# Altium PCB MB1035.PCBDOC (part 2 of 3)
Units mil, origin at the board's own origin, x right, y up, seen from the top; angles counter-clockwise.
Board outline 2598.43 x 3818.9 mil, 2 copper layers (TOP, Bottom); 145 components, 171 nets, 593 pads, 200 vias.
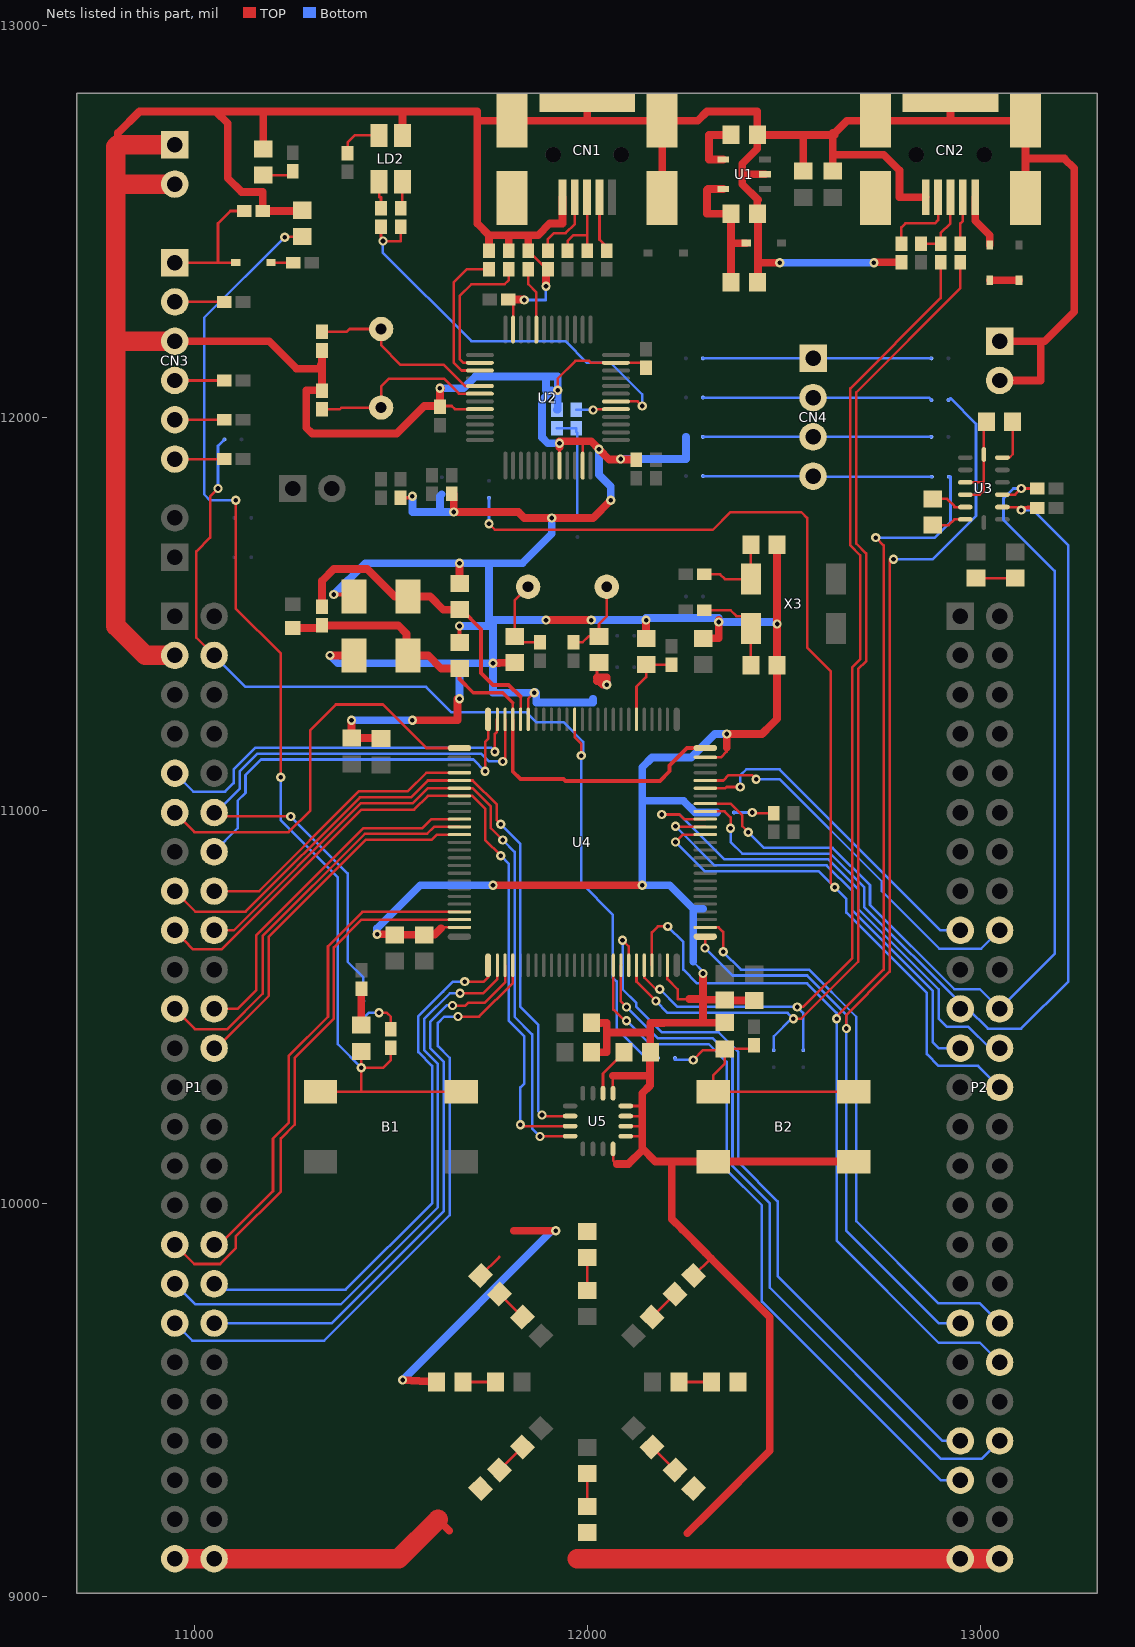
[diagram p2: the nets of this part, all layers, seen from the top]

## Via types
v1: diameter 23.62, hole 11.81, TOP to Bottom, 199 vias
v2: diameter 50, hole 27.56, TOP to Bottom, 1 vias

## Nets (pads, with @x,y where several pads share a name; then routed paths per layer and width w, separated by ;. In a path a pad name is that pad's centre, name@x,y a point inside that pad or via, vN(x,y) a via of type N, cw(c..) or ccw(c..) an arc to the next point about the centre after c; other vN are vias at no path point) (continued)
GND: B2.3 B2.4 C1.1 C2.1 C3.1 C4.1 C5.1 C6.2 C7.1 C8.2 C9.1 C10.1 C11.1 C12.1 C13.1 C14.2 C16.2 C17.1 C18.1 C19.1 C20.2 C21.1 C22.1 C23.1 C24.2 C25.1 C26.2 C27.1 C28.1 C29.1 C30.1 C31.2 C32.2 C34.1 C35.1 C36.1 C37.1 C38.2 CN1.5 CN1.6 CN1.7 CN1.8 CN1.9 CN1.10 CN2.5 CN2.6 CN2.7 CN2.8 CN2.9 CN2.10 CN3.3 JP1.1 JP1.2 JP2.1 JP2.2 LD1.2 LD2.1 LD3.2 LD4.2 LD5.2 LD6.2 LD7.2 LD8.2 LD9.2 LD10.2 P1.3 P1.49 P1.50 P2.49 P2.50 R3.2 R4.1 R8.1 R9.1 R10.1 R11.2 R15.2 R25.1 SB6.2 SB11.1 SB19.1 U1.2 U2.8 U2.20 U2.23 U2.35 U2.47 U3.7 U3.10 U3.11 U4.20 U4.49 U4.74 U4.99 U5.8 U5.9 U5.10 U5.11 U5.12 U5.13 | length 25136.8
  TOP w6.5: C10.1@11623.93,12029.92 11653.93,12029.92 11661.96,12021.9 U2.8@11725.71,12021.9 ; 11626.77,10699.92 11629.34,10702.49 U4.49@11673.69,10702.49 ; LD4.2@11727.78,9816.07 11775.28,9863.57 ; C5.1@11798.99,12299.98 11810.35,12288.63 U2.47@11810.35,12224.65 ; U4.20@11848.89,11232.02 11848.89,11284.88 v1(11863.93,11299.92) ; R10.1@11848.93,12425.04 11897.56,12376.42 R11.2@11898.93,12377.8 ; v1(11923.93,12069.92) 11923.93,12099.92 11968.93,12144.92 12003.93,12144.92 12008.85,12140.01 U2.35@12072.16,12140.01 12136.73,12140.01 C8.2@12148.93,12127.8 ; U2.20@11928.46,11878.19 v1@11928.46,11924.92 ; U2.23@11987.52,11878.19 11987.52,11939.92 ; 12023.93,11338.68 12023.93,11376.46 C23.1@12028.93,11376.46 ; 12063.93,10324.92 12063.93,10280.14 U5.13@12064.73,10280.14 ; U5.8@12064.73,10138.41 12064.73,10109.13 12073.93,10099.92 ; U5.9@12097.21,10170.89 12138.93,10170.89 ; U5.10@12097.21,10196.48 12138.93,10196.48 ; U5.11@12097.21,10222.07 12138.93,10222.07 ; U5.12@12097.21,10247.66 12138.93,10247.66 ; U4.74@12203.22,10606.03 12203.22,10570.63 12228.93,10544.92 12228.93,10519.92 12258.93,10519.92 ; LD5.2@12270.08,9816.07 12313.93,9859.92 ; U4.99@12299.68,11135.56 12339.57,11135.56 12353.93,11149.92 12353.93,11159.92 ; U3.11@12961.69,11804.17 12998.19,11804.17 13008.93,11814.92 13008.93,11835.67 ; U3.10@12961.69,11835.67 13008.93,11835.67 ; C18.1@12988.93,11591.46 C19.1@13088.93,11591.46 ; C11.1@13015.47,11989.92 13008.93,11983.39 U3.7@13008.93,11906.54 13008.93,11835.67
  TOP w9.84: v1(11353.93,11549.92) 11405.04,11549.92 C16.2@11405.04,11544.92 ; C12.1@11523.93,11796.3 11550.31,11796.3 v1(11553.93,11799.92) ; C21.1@11673.93,11428.39 v1(11673.93,11469.92)
  TOP w19.68: 10803.93,12694.92 10803.93,12724.92 10858.93,12779.92 11053.93,12779.92 ; CN3.3@10948.93,12194.92 11188.93,12194.92 11258.93,12124.92 11320.93,12124.92 11320.93,12134.92 ; LD1.2@11173.93,12684.89 11173.93,12779.92 11193.93,12779.92 ; R4.1@11273.93,12528.39 11273.93,12526.42 R3.2@11172.56,12526.42 11172.56,12574.92 11118.93,12574.92 11083.93,12609.92 11083.93,12749.92 11053.93,12779.92 ; C9.1@11323.93,12068.54 C9.1@11323.93,12069.92 ; C7.1@11323.93,12171.3 11323.93,12134.92 11320.93,12134.92 ; v1(11343.93,11394.92) C20.2@11405.04,11394.92 ; v1(11398.93,11229.92) C27.1@11398.93,11184.89 11473.93,11184.89 C28.1@11473.93,11183.39 ; v1(11463.93,10684.92) 11508.93,10684.92 C29.1@11508.93,10683.39 C30.1@11583.93,10683.39 11610.23,10683.39 11626.77,10699.92 ; LD2.1@11528.46,12718.98 11528.46,12779.92 ; v1(11528.93,9549.92) LD6.2@11615.47,9544.92 ; v1(11553.93,11229.92) 11668.93,11229.92 11668.93,11284.92 v1(11673.93,11284.92) ; 11618.93,9194.92 11647.4,9166.46 ; C10.1@11623.93,12028.54 C10.1@11623.93,12029.92 ; v1(11623.93,12074.92) 11626.96,12074.92 11623.93,12077.95 C10.1@11623.93,12029.92 ; R25.1@11653.93,11806.3 11658.93,11806.3 v1(11658.93,11759.92) 11823.93,11759.92 11838.93,11744.92 v1(11908.93,11744.92) 12013.93,11744.92 v1(12058.93,11789.92) ; C17.1@11673.93,11578.39 v1(11673.93,11629.92) ; R8.1@11748.93,12425.04 11748.93,12464.92 ; v1(11758.93,10809.92) v1(12138.93,10809.92) ; v1(11758.93,11374.92) 11774.56,11374.92 11774.56,11376.46 C22.1@11813.93,11376.46 ; C5.1@11797.56,12301.42 C5.1@11800.43,12301.42 ; R9.1@11798.93,12425.04 11798.93,12464.92 ; C5.1@11798.99,12299.98 11798.99,12302.86 C5.1@11800.43,12301.42 ; 11811.63,9929.92 v1(11918.93,9929.92) ; v1(11838.93,12299.92) 11838.93,12301.42 C5.1@11800.43,12301.42 ; R10.1@11848.93,12425.04 11848.93,12464.92 ; v1(11893.93,11484.92) v1(12008.93,11484.92) ; v1(11893.93,12334.92) 11893.93,12376.42 R11.2@11897.56,12376.42 ; v1@11928.46,11924.92 v1(11928.46,11934.92) 11928.46,11939.92 11987.52,11939.92 12008.93,11939.92 v1(12028.93,11919.92) 12055.31,11893.54 v1@12083.93,11893.54 ; CN1.5@11935.82,12561.66 11935.82,12494.92 11903.93,12494.92 11873.93,12464.92 11848.93,12464.92 ; LD3.2@11998.93,9928.39 LD3.2@11998.93,9929.92 ; CN1.10@11998.93,12801.81 11998.93,12756.54 ; C35.1@12009.81,10384.28 12048.93,10384.28 12048.93,10434.92 ; C34.1@12009.81,10459.28 12033.93,10459.28 12033.93,10459.92 12048.93,10459.92 12048.93,10459.28 12048.93,10434.92 ; 12023.93,11329.92 12033.93,11329.92 12033.93,11324.92 12038.93,11324.92 12038.93,11319.92 v1(12048.93,11319.92) 12048.93,11324.92 12048.93,11338.68 12038.93,11338.68 12033.93,11338.68 12023.93,11338.68 ; 12063.93,10324.92 12158.93,10324.92 ; 12073.93,10099.92 12103.93,10099.92 12138.93,10134.92 12138.93,10139.92 ; v1(12083.93,11894.92) v1@12083.93,11893.54 ; C13.1@12123.93,11893.54 v1@12083.93,11893.54 ; C24.2@12148.93,11438.39 v1(12148.93,11484.92) ; 12159.81,10459.92 12159.81,10459.28 ; CN1.8@12189.77,12559.69 CN1.9@12189.77,12756.54 ; 12253.93,9159.92 12308.93,9214.92 12463.93,9369.92 12463.93,9549.92 12463.93,9709.92 12313.93,9859.92 12298.93,9874.92 12240.47,9933.39 12213.93,9959.92 12213.93,10106.34 ; 12258.93,10519.92 12268.93,10519.92 12293.93,10519.92 ; v1(12293.93,10584.92) 12293.93,10574.92 12293.93,10564.92 12293.93,10519.92 ; C25.1@12293.93,11438.39 12333.93,11438.39 v1(12333.93,11479.92) v1@12333.93,11484.92 ; C37.1@12348.93,10459.89 12293.93,10459.89 ; 12353.93,11159.92 v1(12353.93,11194.92) 12443.93,11194.92 12468.93,11219.92 12482.4,11233.39 C26.2@12482.4,11369.92 v1(12482.4,11474.92) C14.2@12482.4,11676.42 ; C32.2@12423.93,10516.46 12348.93,10516.46 C31.2@12348.93,10517.96 12293.93,10517.96 ; C6.2@12432.04,12344.8 12432.04,12344.92 12433.93,12344.92 12433.93,12394.92 ; U1.2@12451.73,12619.96 12393.93,12619.96 ; v1(12488.93,12394.92) 12433.93,12394.92 ; C3.1@12548.82,12628.39 12548.82,12720.12 ; C4.1@12623.93,12628.39 12623.93,12669.92 ; B2.4@12678.07,10106.34 B2.3@12319.8,10106.34 12213.93,10106.34 ; v1(12728.93,12394.92) 12728.93,12396.3 R15.2@12798.93,12396.3 ; CN2.5@12860.82,12561.66 12793.93,12561.66 12793.93,12629.92 12753.93,12669.92 12623.93,12669.92 ; CN2.10@12923.93,12801.81 12923.93,12756.54 ; JP2.2@13048.93,12094.92 13153.93,12094.92 13153.93,12194.92 ; JP2.1@13048.93,12194.92 13153.93,12194.92 ; CN2.8@13114.77,12559.69 13114.77,12659.92 ; 11053.93,12779.92 11193.93,12779.92 ; 11193.93,12779.92 11528.46,12779.92 ; 11320.93,12134.92 11323.93,12137.92 C9.1@11323.93,12069.92 ; C9.1@11323.93,12069.92 11283.93,12069.92 11283.93,11974.92 11298.93,11959.92 11513.93,11959.92 11583.93,12029.92 C10.1@11623.93,12029.92 ; 11528.46,12779.92 11718.93,12779.92 11718.93,12756.54 ; 11718.93,12756.54 11718.93,12494.92 11748.93,12464.92 ; 11718.93,12756.54 CN1.7@11807.88,12756.54 11998.93,12756.54 ; 11748.93,12464.92 11798.93,12464.92 ; 11798.93,12464.92 11848.93,12464.92 ; 11998.93,12756.54 CN1.9@12189.77,12756.54 ; 12048.93,10434.92 12159.81,10434.92 ; 12138.93,10139.92 12138.93,10170.89 12138.93,10196.48 12138.93,10222.07 12138.93,10247.66 12138.93,10279.92 12158.93,10299.92 12158.93,10324.92 ; 12138.93,10139.92 12172.52,10106.34 12213.93,10106.34 ; 12158.93,10324.92 12158.93,10379.28 12163.93,10384.28 C36.1@12159.81,10384.28 12159.81,10434.92 ; 12159.81,10434.92 12159.81,10459.28 ; 12159.81,10459.28 12193.29,10459.28 12193.93,10459.92 12293.93,10459.92 ; CN1.9@12189.77,12756.54 12280.55,12756.54 12303.93,12779.92 12432.04,12779.92 C1.1@12432.04,12720.12 ; 12293.93,10459.92 12293.93,10517.96 ; 12293.93,10517.96 12293.93,10519.92 ; 12393.93,12619.96 12393.93,12594.92 12433.93,12554.92 12432.04,12554.92 C2.1@12432.04,12519.8 12433.93,12519.8 12433.93,12394.92 ; 12393.93,12619.96 12393.93,12646.81 12432.04,12684.92 C1.1@12432.04,12720.12 ; C1.1@12432.04,12720.12 12548.82,12720.12 ; 12548.82,12720.12 12624.13,12720.12 ; 12623.93,12669.92 12623.93,12724.92 12628.74,12720.12 12624.13,12720.12 ; 12624.13,12720.12 12660.55,12756.54 CN2.7@12732.88,12756.54 12923.93,12756.54 ; 12923.93,12756.54 CN2.9@13114.77,12756.54 13114.77,12659.92 ; 13114.77,12659.92 13213.93,12659.92 13238.93,12634.92 13238.93,12269.92 13163.93,12194.92 13153.93,12194.92
  TOP w50: P1.49@10948.93,9094.92 P1.50@11048.93,9094.92 11518.93,9094.92 11618.93,9194.92 ; P1.3@10948.93,11394.92 10873.93,11394.92 10798.93,11469.92 10798.93,12194.92 ; CN3.3@10948.93,12194.92 10798.93,12194.92 ; JP1.2@10948.93,12594.92 10798.93,12594.92 ; JP1.1@10948.93,12694.92 10803.93,12694.92 10798.93,12689.92 10798.93,12594.92 ; 11973.93,9094.92 P2.49@12948.93,9094.92 P2.50@13048.93,9094.92 ; 10798.93,12194.92 10798.93,12594.92
  Bottom w6.5: v1(11838.93,12299.92) 11893.93,12299.92 v1(11893.93,12334.92) ; v1(12138.93,10809.92) v1@12138.93,10814.92 ; 12268.93,10644.92 12268.93,10614.92 12293.93,10589.92 v1(12293.93,10584.92)
  Bottom w19.68: v1(11343.93,11394.92) 11363.93,11374.92 11673.93,11374.92 ; v1(11353.93,11549.92) 11433.93,11629.92 v1(11673.93,11629.92) 11748.93,11629.92 ; v1(11398.93,11229.92) v1(11553.93,11229.92) ; v1(11463.93,10684.92) 11463.93,10699.92 11573.93,10809.92 v1(11758.93,10809.92) ; v1(11528.93,9549.92) 11908.93,9929.92 v1(11918.93,9929.92) ; v1(11553.93,11799.92) 11553.93,11759.92 11623.93,11759.92 ; v1(11623.93,12074.92) 11683.93,12074.92 11713.93,12104.92 11888.93,12104.92 ; SB11.1@11628.93,11805.24 11623.93,11800.24 11623.93,11759.92 ; v1(11658.93,11759.92) 11623.93,11759.92 ; v1(11673.93,11284.92) 11673.93,11374.92 ; v1(11673.93,11469.92) 11748.93,11469.92 ; v1(11893.93,11484.92) 11758.93,11484.92 11758.93,11469.92 ; v1(11908.93,11744.92) 11908.93,11704.92 11833.93,11629.92 11748.93,11629.92 ; C38.2@11921.93,12020.54 11923.93,12020.54 v1(11923.93,12069.92) 11923.93,12104.92 11888.93,12104.92 ; v1(11928.46,11934.92) 11898.93,11934.92 11883.93,11949.92 11883.93,12044.92 11908.93,12069.92 11893.93,12069.92 11893.93,12099.92 11888.93,12104.92 ; v1(12008.93,11484.92) 12018.93,11484.92 v1(12148.93,11484.92) 12148.93,11489.92 12333.93,11489.92 12333.93,11484.92 v1(12333.93,11479.92) v1@12482.4,11479.92 ; 12013.93,11284.92 12013.93,11274.92 11868.93,11274.92 11868.93,11284.92 11868.93,11299.92 11866.43,11302.42 v1(11863.93,11299.92) 11758.93,11299.92 v1(11758.93,11374.92) ; v1(12028.93,11919.92) 12028.93,11854.92 12058.93,11824.92 v1(12058.93,11789.92) ; v1@12043.93,11319.92 v1(12048.93,11319.92) v1@12048.93,11324.92 ; v1(12083.93,11894.92) 12250.31,11894.92 SB6.2@12250.31,11951.42 ; v1(12138.93,10809.92) 12208.93,10809.92 12268.93,10749.92 ; v1@12138.93,10814.92 12138.93,11024.92 ; 12268.93,10614.92 12268.93,10644.92 12268.93,10749.92 ; 12293.93,10749.92 12268.93,10749.92 ; SB19.1@12329.25,10994.92 12273.93,10994.92 12243.93,11024.92 12138.93,11024.92 ; v1(12353.93,11194.92) 12323.93,11194.92 12263.93,11134.92 12163.93,11134.92 12138.93,11109.92 12138.93,11024.92 ; v1(12482.4,11474.92) v1@12482.4,11479.92 ; v1@12482.4,11484.92 v1@12482.4,11479.92 ; v1(12488.93,12394.92) v1(12728.93,12394.92) ; 11673.93,11374.92 v1(11758.93,11374.92) ; 11748.93,11469.92 11758.93,11469.92 ; 11748.93,11469.92 11748.93,11629.92 ; v1(11758.93,11374.92) 11758.93,11469.92
LED_STLINK: R5.1 R6.1 U2.30 | length 1061.9
  TOP w6.5: R5.1@11473.93,12486.3 11473.93,12458.65 v1@11482.66,12449.92 ; v1(11478.93,12449.92) v1@11482.66,12449.92 ; R6.1@11523.97,12486.06 11523.97,12449.92 v1@11482.66,12449.92 ; U2.30@12072.16,12041.58 12127.28,12041.58 v1(12138.93,12029.92)
  Bottom w6.5: v1(11478.93,12449.92) 11478.93,12419.92 11703.93,12194.92 11943.93,12194.92 11998.93,12139.92 12058.93,12139.92 12138.93,12059.92 v1(12138.93,12029.92)
MCO: C38.1 R48.2 SB12.1 | length 283.9
  Bottom w6.5: C38.1@11921.93,11973.3 11970.93,11973.3 R48.2@11970.93,11972.8 11970.93,11964.92 11973.93,11961.92 SB12.1@11973.93,11739.61
NetB1_2: B1.3 B1.4 C33.1 R4.2 R38.2 | length 3025.2
  TOP w6.5: v1(11103.93,11789.92) 11103.93,11514.92 11218.93,11399.92 v1(11218.93,11084.92) ; v1(11228.93,12459.92) 11233.93,12459.92 11235.47,12461.46 R4.2@11273.93,12461.46 ; B1.4@11319.8,10283.51 11423.93,10283.51 ; C33.1@11423.93,10386.46 v1(11423.93,10344.92) ; R38.2@11498.93,10396.3 11498.93,10364.92 11478.93,10344.92 v1(11423.93,10344.92) ; B1.3@11678.07,10283.51 11423.93,10283.51 ; 11423.93,10283.51 v1(11423.93,10344.92)
  Bottom w6.5: v1(11103.93,11789.92) 11038.93,11789.92 11023.93,11804.92 11023.93,12254.92 v1(11228.93,12459.92) ; v1(11218.93,11084.92) 11218.93,10974.92 11363.93,10829.92 11363.93,10404.92 v1(11423.93,10344.92)
NetB2_1: B2.1 B2.2 C37.2 R39.1 SB23.2 | length 706.4
  TOP w6.5: v1(12268.93,10364.92) 12293.93,10389.92 C37.2@12348.93,10389.92 ; R39.1@12423.93,10402.8 12423.93,10392.96 C37.2@12348.93,10392.96 C37.2@12348.93,10389.92 ; B2.2@12678.07,10283.51 B2.1@12319.8,10283.51 12319.8,10325.79 12348.93,10354.92 C37.2@12348.93,10389.92
  Bottom w6.5: SB23.2@12222.56,10369.92 12222.56,10364.92 v1(12268.93,10364.92)
NetC1_2: C1.2 U1.4 | length 155.4
  TOP w19.68: U1.4@12345.43,12657.36 12308.93,12657.36 12308.93,12720.12 C1.2@12365.11,12720.12
NetC2_2: C2.2 C6.1 D3.1 U1.5 | length 378.9
  TOP w19.68: U1.5@12345.43,12582.56 12306.57,12582.56 12303.93,12579.92 12303.93,12519.8 C2.2@12365.11,12519.8 12365.11,12441.1 ; C6.1@12365.11,12344.8 12365.11,12441.1 ; D3.1@12403.66,12444.69 12368.7,12444.69 12365.11,12441.1
NetC14_2: C11.2 U3.6 | length 112.5
  TOP w6.5: U3.6@13056.18,11898.66 13073.93,11898.66 13082.4,11907.13 C11.2@13082.4,11989.92
NetC15_1: C16.1 C17.2 R31.1 U4.21 | length 841.8
  TOP w6.5: 11828.93,11289.92 11829.21,11289.65 U4.21@11829.21,11232.02
  TOP w9.84: C16.1@11538.93,11544.92 C16.1@11542.83,11544.92 ; C17.2@11678.93,11511.46 11728.93,11461.46 11728.93,11349.92 11758.93,11319.92 11798.93,11319.92 11828.93,11289.92
  TOP w19.68: R31.1@11323.93,11518.54 11323.93,11584.92 11353.93,11614.92 11438.93,11614.92 11508.93,11544.92 C16.1@11538.93,11544.92 ; C16.1@11542.83,11544.92 11598.93,11544.92 11632.4,11511.46 C17.2@11673.93,11511.46 C17.2@11678.93,11511.46
NetC17_1: C14.1 R29.2 X3.4 | length 210.3
  TOP w6.5: R29.2@12297.56,11601.42 12337.43,11601.42 12349.44,11589.42 X3.4@12415.67,11589.41 12415.67,11676.42 C14.1@12415.47,11676.42
NetC18_1: C15.1 U3.13 | length 88.9
  TOP w6.5: C15.1@12878.93,11726.46 12919.21,11726.46 12933.93,11741.18 U3.13@12961.69,11741.18
NetC18_2: C15.2 U3.12 | length 92.6
  TOP w6.5: C15.2@12878.93,11793.39 12915.37,11793.39 12933.83,11774.92 12933.83,11772.68 U3.12@12961.69,11772.68
NetC21_1: C20.1 C21.2 L1.2 R31.2 U4.22 U4.100 | length 1411.5
  TOP w6.5: U4.22@11809.52,11232.02 11809.52,11274.33
  TOP w9.84: R31.2@11317.56,11464.92 R31.2@11323.93,11471.3 ; C21.2@11673.93,11361.46 11673.93,11334.92 11708.93,11299.92 11783.93,11299.92 11809.52,11274.33 ; U4.22@11809.52,11232.02 11809.52,11099.33 11828.93,11079.92 11938.93,11079.92 11943.93,11074.92 12183.93,11074.92 12208.93,11099.92 12208.93,11114.92 12253.19,11159.18 U4.100@12299.68,11159.18
  TOP w19.68: L1.2@11248.93,11464.92 R31.2@11317.56,11464.92 ; R31.2@11323.93,11471.3 11517.56,11471.3 11538.93,11449.92 11538.93,11394.92 C20.1@11542.83,11394.92 11593.93,11394.92 11627.4,11361.46 C21.2@11673.93,11361.46
NetC23_2: C22.2 R32.2 X2.1 | length 211.8
  TOP w6.5: X2.1@11848.57,11569.73 11813.93,11535.09 C22.2@11813.93,11443.39 11828.78,11428.54 R32.2@11878.93,11428.54
NetC24_2: C23.2 R33.2 X2.2 | length 205.6
  TOP w6.5: R33.2@11963.93,11428.54 11987.56,11428.54 12002.4,11443.39 C23.2@12028.93,11443.39 12028.93,11474.92 12048.57,11494.56 X2.2@12048.57,11569.73
NetC25_1: C24.1 R34.1 U4.6 | length 214.7
  TOP w6.5: U4.6@12124.48,11232.02 12124.48,11315.47 12148.93,11339.92 C24.1@12148.93,11371.46 12213.93,11371.46 R34.1@12213.93,11371.3
NetC27_1: C26.1 R30.2 X3.1 | length 249.5
  TOP w6.5: R30.2@12297.56,11509.92 12363.93,11509.92 12378.93,11494.92 12415.67,11494.92 X3.1@12415.67,11463.43 12415.67,11369.92 C26.1@12415.47,11369.92
NetC30_2: C33.2 R37.1 | length 92.9
  TOP w19.68: C33.2@11423.93,10453.39 R37.1@11423.93,10546.3
NetC38_2: C36.2 U5.14 | length 126.4
  TOP w6.5: U5.14@12039.14,10280.14 12039.14,10330.13 12092.88,10383.87 C36.2@12092.88,10384.28
NetCN1_2: CN1.2 R14.1 | length 144.3
  TOP w6.5: CN1.2@12030.32,12561.66 12030.32,12453.54 12048.93,12434.92 R14.1@12048.93,12425.04
NetCN1_3: CN1.3 R12.1 R13.1 | length 217.7
  TOP w6.5: R12.1@11948.93,12425.04 11948.93,12449.92 11963.93,12464.92 11998.82,12464.92 ; CN1.3@11998.82,12561.66 11998.82,12464.92 ; R13.1@11998.93,12425.04 11998.82,12425.04 11998.82,12464.92
NetCN1_4: CN1.4 R11.1 | length 182.5
  TOP w6.5: R11.1@11898.93,12425.04 11898.93,12454.92 11913.93,12469.92 11943.93,12469.92 11967.32,12493.31 CN1.4@11967.32,12561.66
NetCN2_1: CN2.1 D4.1 | length 137.1
  TOP w19.68: CN2.1@12986.82,12561.66 12986.82,12502.04 13023.93,12464.92 D4.1@13023.93,12439.92
NetCN2_2: CN2.2 R18.1 | length 120.8
  TOP w6.5: R18.1@12948.93,12443.54 12948.93,12494.92 12955.32,12501.31 CN2.2@12955.32,12561.66
NetCN2_3: CN2.3 R16.1 R17.1 | length 178.4
  TOP w6.5: R16.1@12848.93,12443.54 R17.1@12898.93,12443.54 12898.93,12469.92 12923.82,12494.81 CN2.3@12923.82,12561.66
NetCN2_4: CN2.4 R15.1 | length 200.7
  TOP w6.5: R15.1@12798.93,12443.54 12798.93,12484.92 12808.93,12494.92 12883.93,12494.92 12892.32,12503.31 CN2.4@12892.32,12561.66
NetCN3_1: CN3.1 D1.1 R3.1 | length 334.4
  TOP w6.5: CN3.1@10948.93,12394.92 11058.93,12394.92 ; D1.1@11103.93,12394.92 11058.93,12394.92 ; R3.1@11125.31,12526.42 11090.43,12526.42 11058.93,12494.92 11058.93,12394.92
NetCN3_2: CN3.2 R19.1 | length 126.4
  TOP w6.5: CN3.2@10948.93,12294.92 R19.1@11075.31,12294.92
NetCN3_4: CN3.4 R20.1 | length 126.4
  TOP w6.5: CN3.4@10948.93,12094.92 R20.1@11075.31,12094.92
NetCN3_5: CN3.5 R21.1 | length 126.4
  TOP w6.5: CN3.5@10948.93,11994.92 R21.1@11075.31,11994.92
NetCN3_6: CN3.6 R22.1 | length 126.4
  TOP w6.5: CN3.6@10948.93,11894.92 R22.1@11075.31,11894.92
NetCN4_1: CN4.1 SB1.2 SB2.1 | length 581.7
  Bottom w6.5: SB2.1@12293.62,12151.42 CN4.1@12573.93,12151.42 SB1.2@12875.31,12151.42
NetCN4_2: CN4.2 SB3.2 SB4.1 | length 584.4
  Bottom w6.5: SB4.1@12293.62,12051.42 CN4.2@12573.93,12051.42 12868.81,12051.42 SB3.2@12875.31,12044.92
NetCN4_3: CN4.3 SB5.2 SB6.1 | length 581.7
  Bottom w6.5: SB6.1@12293.62,11951.42 CN4.3@12573.93,11951.42 SB5.2@12875.31,11951.42
NetCN4_4: CN4.4 SB8.2 SB9.1 | length 583.7
  Bottom w6.5: SB9.1@12293.62,11851.42 CN4.4@12573.93,11851.42 12583.93,11851.42 12585.47,11849.89 SB8.2@12876.73,11849.89
NetD1_2: D1.2 R7.1 | length 56.4
  TOP w6.5: D1.2@11193.93,12394.92 R7.1@11250.31,12394.92
NetD4_2: D4.2 D5.1 | length 75
  TOP w19.68: D4.2@13023.93,12349.92 D5.1@13098.93,12349.92
NetLD1_1: LD1.1 R1.1 | length 79.2
  TOP w6.5: LD1.1@11173.93,12617.96 11239.21,12617.96 R1.1@11249.05,12627.8
NetLD2_2: LD2.2 R6.2 | length 72
  TOP w6.5: R6.2@11523.97,12533.31 11528.46,12533.31 LD2.2@11528.46,12600.87
NetLD2_3: LD2.3 R5.2 | length 71.9
  TOP w6.5: LD2.3@11469.41,12600.87 11469.41,12561.2 11473.93,12561.2 R5.2@11473.93,12533.54
NetLD2_4: LD2.4 R2.1 | length 115.5
  TOP w6.5: R2.1@11388.93,12673.54 11388.93,12701.2 11406.71,12718.98 LD2.4@11469.41,12718.98
NetLD3_1: LD4.1 R40.1 | length 83.1
  TOP w6.5: LD4.1@11775.11,9768.75 R40.1@11833.85,9710.01
NetLD4_1: LD3.1 R41.1 | length 83.1
  TOP w6.5: R41.1@11998.93,9778.39 LD3.1@11998.93,9861.46
NetLD5_1: LD5.1 R42.1 | length 83.1
  TOP w6.5: R42.1@12164.02,9710.01 LD5.1@12222.76,9768.75
NetLD6_1: LD6.1 R43.1 | length 83.1
  TOP w6.5: LD6.1@11682.4,9544.92 R43.1@11765.47,9544.92
NetLD7_1: LD8.1 R45.1 | length 83.1
  TOP w6.5: LD8.1@11775.11,9321.1 R45.1@11833.85,9379.84
NetLD8_1: LD9.1 R47.1 | length 83.1
  TOP w6.5: R47.1@12164.02,9379.84 LD9.1@12222.76,9321.1
NetLD9_1: LD7.1 R44.1 | length 83.1
  TOP w6.5: R44.1@12232.4,9544.92 LD7.1@12315.47,9544.92
NetLD10_1: LD10.1 R46.1 | length 83.1
  TOP w6.5: LD10.1@11998.93,9228.39 R46.1@11998.93,9311.46
NetR7_2: R8.2 U2.3 | length 383.3
  TOP w6.5: U2.3@11725.71,12120.32 11678.93,12120.32 11658.93,12140.32 11658.93,12344.92 11691.81,12377.8 R8.2@11748.93,12377.8
NetR8_2: R9.2 U2.2 | length 385.3
  TOP w6.5: U2.2@11725.71,12140.01 11683.85,12140.01 11673.93,12149.92 11673.93,12309.92 11703.93,12339.92 11788.93,12339.92 11798.93,12349.92 R9.2@11798.93,12377.8
NetR9_2: R10.2 U2.44 | length 161.6
  TOP w6.5: R10.2@11848.93,12377.8 11848.93,12339.92 11869.41,12319.45 U2.44@11869.41,12224.65
NetR23_1: R48.1 U2.29 | length 103.3
  TOP w6.5: v1(12013.93,12019.92) 12013.93,12021.9 U2.29@12072.16,12021.9
  Bottom w6.5: R48.1@11970.93,12020.04 11970.93,12019.92 v1(12013.93,12019.92)
NetR36_1: R35.1 SB19.2 | length 102.8
  TOP w6.5: v1(12418.93,10994.92) 12418.93,10993.54 R35.1@12473.93,10993.54
  Bottom w6.5: SB19.2@12372.56,10994.92 v1(12418.93,10994.92)
NetR39_1: R38.1 SB20.2 | length 111.2
  TOP w6.5: v1(11468.93,10484.92) 11488.93,10484.92 11498.93,10474.92 R38.1@11498.93,10443.54
  Bottom w6.5: SB20.2@11428.93,10471.3 11442.56,10484.92 v1(11468.93,10484.92)
NRST: P1.4 SB7.2 SB23.1 U4.14 | length 2637.1
  TOP w6.5: P1.4@11048.93,11394.92 11003.93,11439.92 11003.93,11659.92 11038.93,11694.92 11038.93,11799.92 v1(11058.93,11819.92) ; U4.14@11967,11232.02 11967,11186.85 11983.93,11169.92 v1(11983.93,11139.92)
  Bottom w6.5: P1.4@11048.93,11394.92 11128.93,11314.92 11588.93,11314.92 11653.93,11249.92 11843.93,11249.92 11868.93,11224.92 11938.93,11224.92 11988.93,11174.92 11988.93,11139.92 v1(11983.93,11139.92) 11983.93,10814.92 12063.93,10734.92 12063.93,10574.92 12073.93,10564.92 12073.93,10444.92 12148.93,10369.92 SB23.1@12179.25,10369.92 ; v1(11058.93,11819.92) 11058.93,11928.54 SB7.2@11075.31,11944.92
OSC_IN: C7.2 U2.5 X1.2 | length 512.9
  TOP w6.5: U2.5@11725.71,12080.95 11687.91,12080.95 11633.93,12134.92 11523.93,12134.92 11474.13,12184.73 X1.2@11474.13,12226.06 11393.93,12226.06 11386.42,12218.54 C7.2@11323.93,12218.54 11323.25,12219.23 C7.2@11323.25,12214.92 ; C7.2@11323.25,12214.92 11322.95,12214.43 11322.95,12221.08 11326.97,12221.08 C7.2@11323.25,12214.92
OSC_OUT: C9.2 U2.6 X1.1 | length 482
  TOP w6.5: C9.2@11323.93,12021.3 11368.93,12021.3 11373.69,12026.06 X1.1@11474.13,12026.06 11474.13,12080.12 11493.93,12099.92 11633.93,12099.92 11672.59,12061.27 U2.6@11725.71,12061.27
PA0: P1.12 SB20.1 U4.23 | length 1696.2
  TOP w6.5: P1.12@11048.93,10994.92 11053.93,10994.92 11063.93,10984.92 v1(11243.93,10984.92) ; v1(11783.93,11124.92) 11789.84,11130.83 U4.23@11789.84,11232.02
  Bottom w6.5: P1.12@11048.93,10994.92 11068.93,10994.92 11068.93,11009.92 11113.93,11054.92 11113.93,11099.92 11158.93,11144.92 11728.93,11144.92 11748.93,11124.92 v1(11783.93,11124.92) ; v1(11243.93,10984.92) 11388.93,10839.92 11388.93,10614.92 11428.93,10574.92 SB20.1@11428.93,10514.61
PA1: P1.9 U4.24 | length 990.8
  TOP w6.5: v1(11763.93,11149.92) 11763.93,11194.92 11769.15,11200.14 11769.15,11232.02 U4.24@11770.15,11232.02
  Bottom w6.5: P1.9@10948.93,11094.92 10995.93,11047.92 11076.93,11047.92 11098.93,11069.92 11098.93,11104.92 11153.93,11159.92 11753.93,11159.92 v1(11763.93,11149.92)
PA2: P1.14 U4.25 | length 1002.4
  TOP w6.5: v1(11738.93,11099.92) 11738.93,11174.92 11746.53,11182.52 U4.25@11746.53,11232.02
  Bottom w6.5: P1.14@11048.93,10894.92 11108.93,10954.92 11108.93,11024.92 11128.93,11044.92 11128.93,11089.92 11168.93,11129.92 11708.93,11129.92 v1(11738.93,11099.92)
PA3: P1.11 U4.26 | length 1046
  TOP w6.5: P1.11@10948.93,10994.92 10998.93,10944.92 11238.93,10944.92 11293.93,10999.92 11293.93,11204.92 11358.93,11269.92 11478.93,11269.92 11589.67,11159.18 U4.26@11673.69,11159.18
PA4: P1.16 U4.29 | length 749.5
  TOP w6.5: P1.16@11048.93,10794.92 11101.75,10794.93 11163.94,10794.93 11418.45,11049.44 11542.47,11049.44 11589.22,11096.19 U4.29@11673.69,11096.19
PA5: P1.15 U4.30 U5.2 | length 1917.3
  TOP w6.5: P1.15@10948.93,10794.92 11001.04,10742.82 11129.37,10742.82 11420.26,11033.7 11550.44,11033.7 11593.25,11076.51 U4.30@11673.69,11076.51 11707.35,11076.51 11768.93,11014.92 11768.93,10974.92 v1(11778.93,10964.92) ; v1(11883.93,10224.92) 11883.93,10222.07 U5.2@11955.48,10222.07
  Bottom w6.5: v1(11778.93,10964.92) 11828.93,10914.92 11828.93,10499.92 11873.93,10454.92 11873.93,10234.92 v1(11883.93,10224.92)
PA6: P1.18 U4.31 U5.4 | length 1845
  TOP w6.5: P1.18@11048.93,10694.92 11078.14,10694.93 11099.03,10694.93 11422.06,11017.96 11554.39,11017.96 11593.25,11056.82 U4.31@11673.69,11056.82 11707.04,11056.82 11753.93,11009.92 11753.93,10954.92 v1(11783.93,10924.92) ; v1(11878.93,10169.92) 11877.97,10170.89 U5.4@11955.48,10170.89
  Bottom w6.5: v1(11783.93,10924.92) 11813.93,10894.92 11813.93,10474.92 11858.93,10429.92 11858.93,10189.92 v1(11878.93,10169.92)
PA7: P1.17 U4.32 U5.3 | length 1964.3
  TOP w6.5: P1.17@10948.93,10694.92 10995.79,10646.42 11068.07,10646.42 11423.87,11002.22 11558.33,11002.22 11593.25,11037.14 U4.32@11673.69,11037.14 11706.72,11037.14 11738.93,11004.92 11738.93,10924.92 v1(11778.93,10884.92) ; v1(11828.93,10199.92) 11832.37,10196.48 U5.3@11955.48,10196.48
  Bottom w6.5: v1(11778.93,10884.92) 11798.93,10864.92 11798.93,10464.92 11838.93,10424.92 11838.93,10304.92 11828.93,10294.92 v1(11828.93,10199.92)
PA8: P2.45 U4.67 | length 1797.2
  TOP w6.5: U4.67@12065.43,10606.03 12065.43,10493.43 12093.93,10464.92 v1(12098.93,10464.92)
  Bottom w6.5: v1(12098.93,10464.92) 12158.93,10404.92 12308.93,10404.92 12353.93,10359.92 12353.93,10084.92 12443.93,9994.92 12443.93,9749.92 12898.93,9294.92 P2.45@12948.93,9294.92
PA9: P2.44 U4.68 | length 1845.5
  TOP w6.5: U4.68@12085.11,10606.03 12083.93,10606.03 12083.93,10514.92 v1(12098.93,10499.92)
  Bottom w6.5: v1(12098.93,10499.92) 12178.93,10419.92 12318.93,10419.92 12368.93,10369.92 12368.93,10094.92 12463.93,9999.92 12463.93,9784.92 12898.93,9349.92 13003.93,9349.92 P2.44@13048.93,9394.92
PA10: P2.43 U4.69 | length 1813
  TOP w6.5: v1(12088.93,10669.92) 12104.8,10654.06 U4.69@12104.8,10606.03
  Bottom w6.5: v1(12088.93,10669.92) 12088.93,10544.92 12123.93,10509.92 12123.93,10499.92 12188.93,10434.92 12333.93,10434.92 12383.93,10384.92 12383.93,10104.92 12483.93,10004.92 12483.93,9814.92 12903.93,9394.92 P2.43@12948.93,9394.92
PA11: R18.2 SB22.1 U4.70 | length 2719
  TOP w6.5: U4.70@12124.48,10606.03 12124.48,10564.37 v1(12173.93,10514.92) ; v1(12523.93,10469.92) 12543.93,10469.92 12688.93,10614.92 12688.93,11359.92 12708.93,11379.92 12708.93,11654.92 12683.93,11679.92 12683.93,12064.92 12948.93,12329.92 R18.2@12948.93,12396.3
  Bottom w6.5: v1(12173.93,10514.92) 12203.93,10484.92 12508.93,10484.92 v1(12523.93,10469.92) 12518.93,10469.92 12473.93,10424.92 SB22.1@12473.93,10389.61
PA12: R17.2 SB21.1 U4.71 | length 2645.7
  TOP w6.5: U4.71@12144.17,10606.03 12144.17,10574.69 12173.93,10544.92 v1(12183.93,10544.92) ; v1(12533.93,10499.92) 12548.93,10499.92 12673.93,10624.92 12673.93,11364.92 12693.93,11384.92 12693.93,11649.92 12668.93,11674.92 12668.93,12074.92 12898.93,12304.92 R17.2@12898.93,12396.3
  Bottom w6.5: v1(12183.93,10544.92) 12228.93,10499.92 v1(12533.93,10499.92) 12548.93,10484.92 SB21.1@12548.93,10389.61
PA13: P2.40 SB8.1 U4.72 | length 3431.2
  TOP w6.5: U4.72@12163.85,10606.03 12163.85,10689.84 12178.93,10704.92 v1(12203.93,10704.92) ; v1(12633.93,10469.92) 12628.93,10469.92 12753.93,10594.92 12753.93,11674.92 v1(12733.93,11694.92)
  Bottom w6.5: v1(12203.93,10704.92) 12243.93,10664.92 12243.93,10594.92 12278.93,10559.92 12558.93,10559.92 12633.93,10484.92 v1(12633.93,10469.92) 12633.93,9904.92 12893.93,9644.92 12998.93,9644.92 P2.40@13048.93,9594.92 ; v1(12733.93,11694.92) 12883.93,11694.92 12923.93,11734.92 12923.93,11849.89 SB8.1@12920.04,11849.89
PA14: P2.37 SB3.1 U4.76 | length 3237.7
  TOP w6.5: v1(12298.93,10649.92) 12299.68,10649.92 U4.76@12299.68,10678.87 ; v1(12658.93,10444.92) 12658.93,10479.92 12768.93,10589.92 12768.93,11639.92 v1(12778.93,11639.92)
  Bottom w6.5: v1(12298.93,10649.92) 12368.93,10579.92 12558.93,10579.92 12658.93,10479.92 v1(12658.93,10444.92) 12658.93,9929.92 12893.93,9694.92 P2.37@12948.93,9694.92 ; v1(12778.93,11639.92) 12878.93,11639.92 12988.93,11749.92 12988.93,11984.61 12923.62,12049.92 SB3.1@12918.62,12044.92
PA15: P2.38 U4.77 | length 1501
  TOP w6.5: U4.77@12299.68,10702.49 12333.79,10702.49 12345.21,10691.07 v1(12345.21,10640.2)
  Bottom w6.5: v1(12345.21,10640.2) 12390.49,10594.92 12563.93,10594.92 12683.93,10474.92 12683.93,9954.92 12893.93,9744.92 12998.93,9744.92 P2.38@13048.93,9694.92
PB0: P1.22 U4.35 | length 906.7
  TOP w6.5: P1.22@11048.93,10494.92 11108.84,10494.93 11156.84,10542.93 11156.84,10682.57 11429.28,10955 11579.26,10955 11602.33,10978.08 U4.35@11673.69,10978.08
PB1: P1.21 U4.36 | length 1045.7
  TOP w6.5: P1.21@10948.93,10494.92 11000.41,10443.45 11082.58,10443.45 11172.58,10533.45 11172.58,10680.76 11432.74,10940.92 11591.51,10940.92 11608.99,10958.4 U4.36@11673.69,10958.4
PB2: P1.24 U4.37 | length 938.2
  TOP w6.5: P1.24@11048.93,10394.92 11054.83,10394.92 11188.32,10528.42 11188.32,10678.96 11435.29,10925.92 11603.5,10925.92 11616.29,10938.71 U4.37@11673.69,10938.71
PB3: P2.26 SB10.2 U4.89 | length 3162.2
  TOP w6.5: v1(11748.93,11729.92) 11763.93,11714.92 12318.93,11714.92 12363.93,11759.92 12543.93,11759.92 12558.93,11744.92 12558.93,11414.92 12618.93,11354.92 12618.93,10814.92 v1(12628.93,10804.92) ; v1(12223.93,10919.92) 12242.72,10938.71 U4.89@12299.68,10938.71
  Bottom w6.5: v1(11748.93,11729.92) 11743.93,11729.92 11748.93,11734.92 SB10.2@11748.93,11796.3 ; v1(12223.93,10919.92) 12299.03,10844.82 12589.03,10844.82 v1(12628.93,10804.92) 12658.93,10774.92 12658.93,10739.92 12863.93,10534.92 12863.93,10379.92 12893.93,10349.92 12993.93,10349.92 P2.26@13048.93,10294.92
PB4: P2.23 U4.90 | length 1140.9
  TOP w6.5: v1(12223.93,10959.92) 12225.46,10958.4 U4.90@12299.68,10958.4
  Bottom w6.5: v1(12223.93,10959.92) 12323.29,10860.56 12608.29,10860.56 12673.93,10794.92 12673.93,10744.92 12878.93,10539.92 12878.93,10409.92 12893.93,10394.92 P2.23@12948.93,10394.92
PB5: P2.24 U4.91 | length 1295.3
  TOP w6.5: v1(12188.93,10989.92) 12233.93,10989.92 12245.78,10978.08 U4.91@12299.68,10978.08
  Bottom w6.5: v1(12188.93,10989.92) 12233.93,10989.92 12347.55,10876.3 12612.55,10876.3 12688.93,10799.92 12688.93,10749.92 12893.93,10544.92 12893.93,10469.92 12913.93,10449.92 12968.93,10449.92 13023.93,10394.92 P2.24@13048.93,10394.92
PB6: P2.21 R28.2 U3.2 U4.92 | length 2690
  TOP w6.5: U4.92@12299.68,10997.77 12348.93,10997.77 12363.93,10982.77 v1(12363.93,10954.92) ; U3.2@13056.18,11772.68 v1@13103.93,11772.68 ; v1(13103.93,11764.92) v1@13103.93,11772.68 ; R28.2@13145.31,11769.92 13117.66,11769.92 13121.06,11773.33 13137.66,11773.33 13138.31,11772.68 v1@13103.93,11772.68
  Bottom w6.5: v1(12363.93,10954.92) 12363.93,10919.92 12393.93,10889.92 12618.93,10889.92 12703.93,10804.92 12703.93,10754.92 12948.93,10509.92 P2.21@12948.93,10494.92 ; v1(13103.93,11764.92) 13133.93,11764.92 13223.93,11674.92 13223.93,10564.92 13103.93,10444.92 13018.93,10444.92 12968.93,10494.92 P2.21@12953.93,10494.92 ; P2.21@12948.93,10494.92 P2.21@12953.93,10494.92 ; P2.21@12948.93,10494.92 P2.21@12953.93,10494.92
PB7: P2.22 R27.2 U3.3 U4.93 | length 2574
  TOP w6.5: U4.93@12299.68,11017.45 12363.93,11017.45 12393.93,10987.45 12393.93,10959.92 v1(12408.93,10944.92) ; U3.3@13056.18,11804.17 13088.19,11804.17 v1(13103.93,11819.92) R27.2@13145.31,11819.92
  Bottom w6.5: v1(12408.93,10944.92) 12448.93,10904.92 12623.93,10904.92 12718.93,10809.92 12718.93,10759.92 12933.93,10544.92 12998.93,10544.92 P2.22@13048.93,10494.92 13188.93,10634.92 13188.93,11609.92 13058.93,11739.92 13058.93,11794.92 13083.93,11819.92 v1(13103.93,11819.92)
PB8: P2.17 U4.95 | length 856.6
  TOP w6.5: U4.95@12299.68,11056.82 12350.83,11056.82 12353.93,11059.92 v1(12388.93,11059.92)
  Bottom w6.5: v1(12388.93,11059.92) 12388.93,11089.92 12403.93,11104.92 12488.93,11104.92 12898.93,10694.92 P2.17@12948.93,10694.92
PB9: P2.18 U4.96 | length 971.9
  TOP w6.5: U4.96@12299.68,11076.51 12345.52,11076.51 12358.93,11089.92 12418.93,11089.92 v1(12428.93,11079.92)
  Bottom w6.5: v1(12428.93,11079.92) 12488.93,11079.92 12748.93,10819.92 12748.93,10794.92 12895.78,10648.07 13002.08,10648.07 P2.18@13048.93,10694.92
PB10: P1.34 U4.47 | length 1258.6
  TOP w6.5: P1.34@11048.93,9894.92 11062.93,9894.92 11198.93,10030.92 11198.93,10164.92 11238.93,10204.92 11238.93,10374.92 11338.93,10474.92 11338.93,10654.13 11426.67,10741.86 U4.47@11673.69,10741.86
PB11: P1.33 U4.48 | length 1411.1
  TOP w6.5: P1.33@10948.93,9894.92 10998.47,9845.38 11064.39,9845.38 11103.93,9884.92 11103.93,9914.92 11218.93,10029.92 11218.93,10164.92 11253.93,10199.92 11253.93,10369.92 11353.93,10469.92 11353.93,10651.58 11424.52,10722.18 U4.48@11673.69,10722.18
PB12: P1.36 U4.51 | length 1401.6
  TOP w6.5: v1(11686.93,10564.42) 11735.94,10564.42 11746.53,10575.01 U4.51@11746.53,10606.03
  Bottom w6.5: P1.36@11048.93,9794.92 11048.93,9779.92 11383.93,9779.92 11603.93,9999.92 11603.93,10349.92 11568.93,10384.92 11568.93,10476.42 11631.48,10538.97 11632.01,10538.97 11657.47,10564.42 v1(11686.93,10564.42)
PB13: P1.35 U4.52 | length 1551.3
  TOP w6.5: v1(11674.93,10534.42) 11733.15,10534.42 11770.15,10571.42 U4.52@11770.15,10606.03
  Bottom w6.5: P1.35@10948.93,9794.92 11001.43,9742.42 11371.43,9742.42 11618.93,9989.92 11618.93,10354.92 11583.93,10389.92 11583.93,10469.42 11648.93,10534.42 v1(11674.93,10534.42)
PB14: P1.38 U4.53 | length 1476.2
  TOP w6.5: v1(11655.93,10503.42) 11688.96,10503.42 11695.96,10510.42 11737.76,10510.42 11789.84,10562.5 U4.53@11789.84,10606.03
  Bottom w6.5: P1.38@11048.93,9694.92 11348.93,9694.92 11633.93,9979.92 11633.93,10359.92 11598.93,10394.92 11598.93,10461.42 11641.93,10504.42 11654.93,10504.42 v1(11655.93,10503.42)
PB15: P1.37 U4.54 | length 1630.8
  TOP w6.5: v1(11669.93,10475.42) 11723.97,10475.42 11809.52,10560.97 U4.54@11809.52,10606.03
  Bottom w6.5: P1.37@10948.93,9694.92 10993.93,9649.92 11328.93,9649.92 11648.93,9969.92 11648.93,10369.92 11618.93,10399.92 11618.93,10459.42 11634.93,10475.42 v1(11669.93,10475.42)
